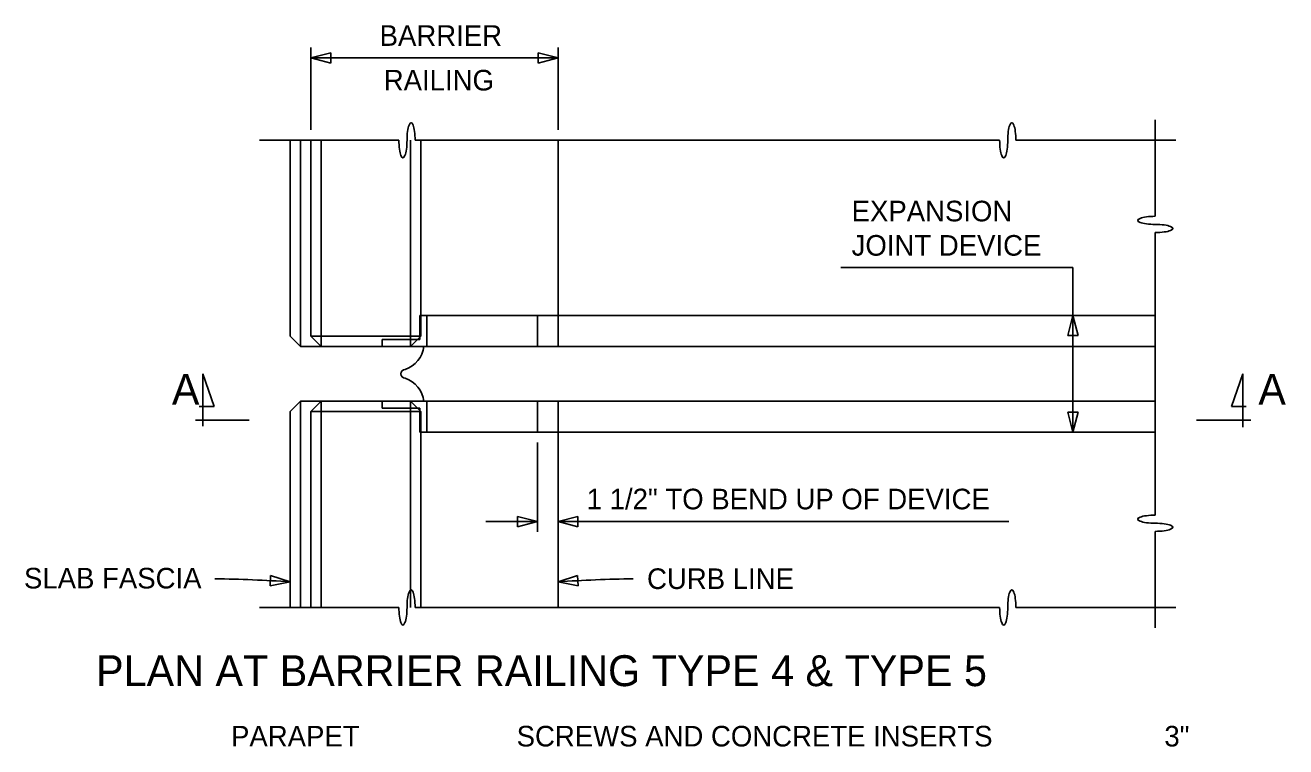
# Model space of a CAD drawing. Extents: x 19590 to 20151, y 19944 to 20103.
# Drawn here: x 19615.15 to 19643.46, y 20077.95 to 20094.14 of the extents above; entities that cross this region are included whole.
import ezdxf

# ---------------------------------------------------------------- set-up
doc = ezdxf.new("R2010")
doc.units = 0
for name, color, linetype in [('DETAIL_PR', 7, 'Continuous'), ('DETAIL_TEXT_DIMEN_PR', 7, 'Continuous'), ('Level 1', 7, 'Continuous')]:
    doc.layers.add(name, color=color, linetype=linetype)

msp = doc.modelspace()

# ---------------------------------------------------------------- linework, layer by layer
at = {"layer": 'DETAIL_PR'}
for p, q in [((19640.527, 20092.024), (19640.527, 20089.855)), ((19620.408, 20091.561), (19623.541, 20091.561)), ((19621.102, 20091.562), (19621.102, 20087.168)), ((19621.333, 20091.562), (19621.333, 20086.937)), ((19621.565, 20091.562), (19621.565, 20087.168)), ((19621.796, 20091.562), (19621.796, 20086.937)), ((19623.8, 20091.562), (19623.8, 20086.937)), ((19623.905, 20091.561), (19637.031, 20091.561)), ((19624.031, 20091.562), (19624.031, 20087.168)), ((19627.115, 20091.561), (19627.115, 20086.936)), ((19637.395, 20091.561), (19640.99, 20091.561)), ((19640.527, 20089.491), (19640.527, 20084.855)), ((19624.012, 20087.091), (19624.012, 20087.63)), ((19624.012, 20087.63), (19627.115, 20087.63)), ((19624.166, 20086.936), (19624.166, 20087.63)), ((19626.652, 20086.936), (19626.652, 20087.63)), ((19627.115, 20087.63), (19640.527, 20087.63)), ((19621.333, 20086.936), (19621.102, 20087.168)), ((19621.565, 20087.168), (19624.031, 20087.168)), ((19621.565, 20087.168), (19621.796, 20086.936)), ((19624.031, 20087.168), (19623.8, 20086.936)), ((19621.333, 20086.937), (19623.164, 20086.937)), ((19623.164, 20086.936), (19623.164, 20087.091)), ((19623.164, 20087.091), (19624.012, 20087.091)), ((19623.164, 20086.936), (19640.527, 20086.936)), ((19621.333, 20085.703), (19621.102, 20085.472)), ((19621.102, 20081.078), (19621.102, 20085.472)), ((19621.333, 20085.703), (19623.164, 20085.703)), ((19621.333, 20081.078), (19621.333, 20085.703)), ((19621.565, 20085.472), (19621.796, 20085.703)), ((19621.565, 20081.078), (19621.565, 20085.472)), ((19621.565, 20085.472), (19624.031, 20085.472)), ((19621.796, 20081.078), (19621.796, 20085.703)), ((19623.164, 20085.703), (19623.164, 20085.549)), ((19623.164, 20085.703), (19640.527, 20085.703)), ((19623.164, 20085.549), (19624.012, 20085.549)), ((19623.8, 20081.078), (19623.8, 20085.703)), ((19624.031, 20085.472), (19623.8, 20085.703)), ((19624.012, 20085.549), (19624.012, 20085.009)), ((19624.031, 20081.078), (19624.031, 20085.472)), ((19624.166, 20085.703), (19624.166, 20085.009)), ((19626.652, 20085.009), (19626.652, 20085.703)), ((19627.115, 20081.078), (19627.115, 20085.703)), ((19624.012, 20085.009), (19627.115, 20085.009)), ((19627.115, 20085.009), (19640.527, 20085.009)), ((19640.527, 20083.149), (19640.527, 20084.855)), ((19640.527, 20082.785), (19640.527, 20080.616)), ((19620.408, 20081.078), (19623.541, 20081.078)), ((19623.905, 20081.078), (19637.031, 20081.078)), ((19637.395, 20081.078), (19640.99, 20081.078))]:
    msp.add_line(p, q, dxfattribs=at)
for centre, radius, start, end in [((19623.49, 20087.001), 0.612, 288.1365, 353.9316), ((19623.688, 20086.32), 0.0999, 94.4387, 265.5613), ((19623.49, 20085.638), 0.612, 6.0684, 71.8635)]:
    msp.add_arc(centre, radius, start, end, dxfattribs=at)
for centre, major_axis, ratio, start_param, end_param in [((19623.814, 20091.561), (0, -0.395), 0.230204, 1.570796, 4.712389), ((19637.304, 20091.561), (0, -0.395), 0.230204, 1.570796, 4.712389), ((19623.632, 20091.561), (0, -0.395), 0.230206, 4.712389, 7.853982), ((19637.122, 20091.561), (0, -0.395), 0.230206, 4.712389, 7.853982), ((19640.527, 20089.764), (0.395, 0), 0.230204, 1.570796, 4.712389), ((19640.527, 20089.582), (0.395, 0), 0.230206, 4.712389, 7.853982), ((19640.527, 20083.058), (0.395, 0), 0.230204, 1.570796, 4.712389), ((19640.527, 20082.876), (0.395, 0), 0.230206, 4.712389, 7.853982), ((19623.814, 20081.078), (0, -0.395), 0.230204, 1.570796, 4.712389), ((19637.304, 20081.078), (0, -0.395), 0.230204, 1.570796, 4.712389), ((19623.632, 20081.078), (0, -0.395), 0.230206, 4.712389, 7.853982), ((19637.122, 20081.078), (0, -0.395), 0.230206, 4.712389, 7.853982)]:
    msp.add_ellipse(centre, major_axis=major_axis, ratio=ratio, start_param=start_param, end_param=end_param, dxfattribs=at)
at = {"layer": 'DETAIL_TEXT_DIMEN_PR'}
for p, q in [((19621.565, 20091.793), (19621.565, 20093.643)), ((19627.115, 20091.793), (19627.115, 20093.643)), ((19621.565, 20093.411), (19627.115, 20093.411)), ((19633.465, 20088.709), (19638.677, 20088.709)), ((19638.677, 20088.709), (19638.677, 20085.009)), ((19619.137, 20085.149), (19619.136, 20086.32)), ((19619.136, 20086.32), (19619.389, 20085.584)), ((19642.493, 20086.32), (19642.239, 20085.584)), ((19642.492, 20085.122), (19642.493, 20086.32)), ((19619.389, 20085.584), (19619.059, 20085.584)), ((19642.239, 20085.584), (19642.57, 20085.584)), ((19620.177, 20085.279), (19618.971, 20085.279)), ((19641.452, 20085.279), (19642.668, 20085.279)), ((19626.652, 20082.774), (19626.652, 20084.778)), ((19625.496, 20083.005), (19626.652, 20083.005)), ((19627.115, 20083.005), (19637.238, 20083.005))]:
    msp.add_line(p, q, dxfattribs=at)
for centre, start, end in [((19618.675, 20042.578), 86.4465, 88.9222), ((19629.541, 20042.578), 91.0778, 93.5535)]:
    msp.add_arc(centre, 39.151, start, end, dxfattribs=at)
at = {"layer": 'Level 1'}
for p, q in [((19622.012, 20093.527), (19621.565, 20093.412)), ((19621.565, 20093.412), (19622.012, 20093.296)), ((19622.012, 20093.296), (19622.012, 20093.527)), ((19626.666, 20093.296), (19626.666, 20093.527)), ((19626.666, 20093.527), (19627.115, 20093.412)), ((19627.115, 20093.412), (19626.666, 20093.296)), ((19638.677, 20087.63), (19638.561, 20087.182)), ((19638.793, 20087.182), (19638.677, 20087.63)), ((19638.561, 20087.182), (19638.793, 20087.182)), ((19638.793, 20085.457), (19638.561, 20085.457)), ((19638.561, 20085.457), (19638.677, 20085.009)), ((19638.677, 20085.009), (19638.793, 20085.457)), ((19626.204, 20082.89), (19626.204, 20083.121)), ((19626.204, 20083.121), (19626.652, 20083.005)), ((19626.652, 20083.005), (19626.204, 20082.89)), ((19627.562, 20083.121), (19627.115, 20083.005)), ((19627.115, 20083.005), (19627.562, 20082.89)), ((19627.562, 20082.89), (19627.562, 20083.121)), ((19620.661, 20081.794), (19620.648, 20081.564)), ((19621.102, 20081.654), (19620.661, 20081.794)), ((19627.115, 20081.654), (19627.555, 20081.794)), ((19627.555, 20081.794), (19627.568, 20081.564)), ((19620.648, 20081.564), (19621.102, 20081.654)), ((19627.568, 20081.564), (19627.115, 20081.654))]:
    msp.add_line(p, q, dxfattribs=at)

# ---------------------------------------------------------------- texts
at = {"layer": 'DETAIL_TEXT_DIMEN_PR'}
for s, height, p in [('BARRIER', 0.4625, (19623.108, 20093.681)), ('RAILING', 0.4625, (19623.201, 20092.679)), ('EXPANSION ', 0.4625, (19633.707, 20089.742)), ('JOINT DEVICE', 0.4625, (19633.707, 20088.972)), ('A', 0.694, (19618.443, 20085.626)), ('A', 0.694, (19642.84, 20085.626)), ('1 1/2" TO BEND UP OF DEVICE', 0.4625, (19627.758, 20083.279)), ('SLAB FASCIA', 0.4625, (19615.122, 20081.503)), ('CURB LINE', 0.4625, (19629.113, 20081.491)), ('PLAN AT BARRIER RAILING TYPE 4 & TYPE 5', 0.69385, (19616.74, 20079.311)), ('PARAPET', 0.4625, (19619.771, 20077.957)), ('SCREWS AND CONCRETE INSERTS', 0.4625, (19626.185, 20077.957)), ('3"', 0.4625, (19640.73, 20077.957))]:
    msp.add_text(s, height=height, dxfattribs=at).set_placement(p)

doc.saveas('drawing.dxf')
